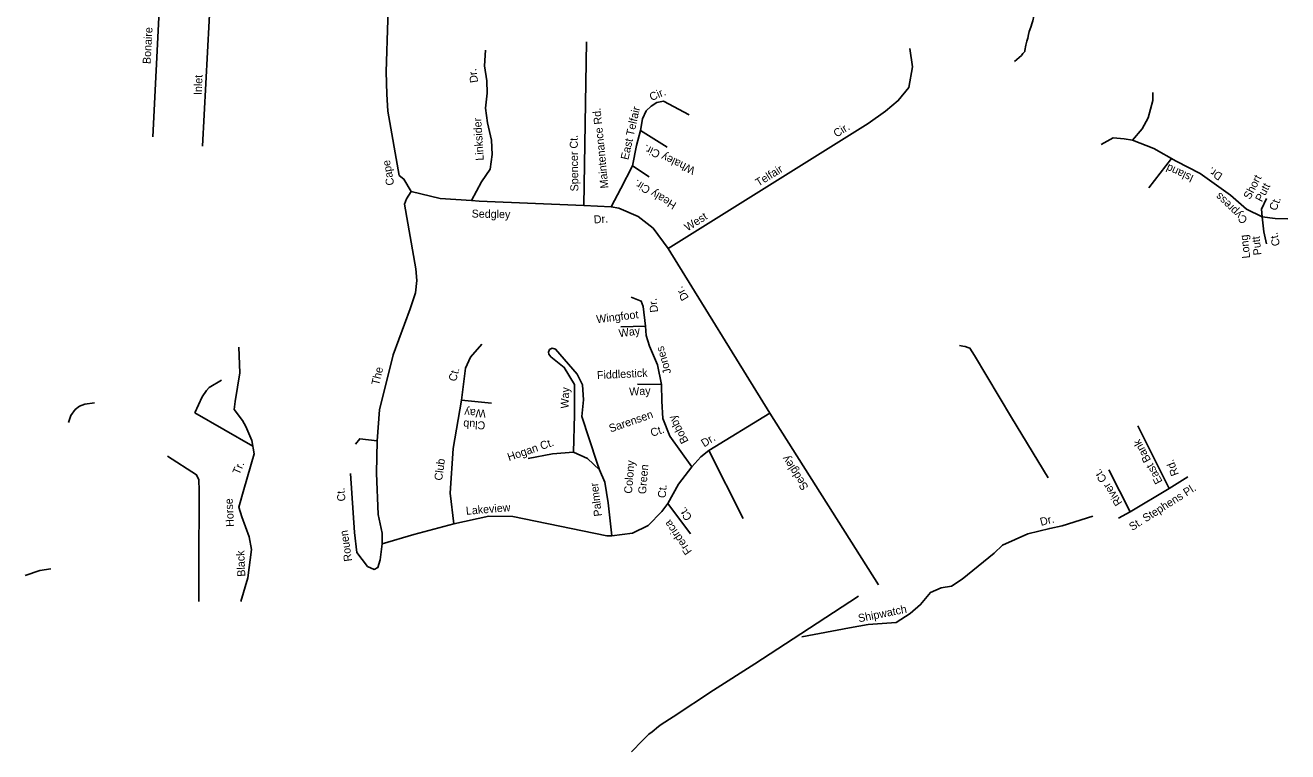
# Model space of a CAD drawing. Extents: x 2308163 to 2335412, y -96774 to 125428.
# Drawn here: x 2324630 to 2334985, y -96774 to -90814 of the extents above; entities that cross this region are included whole.
import ezdxf

# ---------------------------------------------------------------- set-up
doc = ezdxf.new("R2010")
doc.units = 0
doc.layers.add('Old_Level_10', color=7, linetype='Continuous')
doc.layers.add('Old_Level_35', color=7, linetype='Continuous')

msp = doc.modelspace()

# ---------------------------------------------------------------- linework, layer by layer
at = {"layer": 'Old_Level_35'}
for points in [[(2326085, -91806), (2326152, -90518), (2326189, -90072), (2326190, -89610), (2326229, -89135), (2326193, -88679), (2326196, -88378), (2326271, -88124), (2326301, -87898), (2326305, -87568)], [(2325677, -91728), (2325865, -87971), (2325825, -87640)], [(2327796, -92178), (2327736, -92075), (2327696, -92045), (2327605, -91518), (2327597, -91379), (2327591, -91195), (2327605, -90768), (2327601, -90659), (2327585, -90390), (2327568, -90164), (2327576, -90042), (2327622, -89922), (2327719, -89796), (2327790, -89673), (2327855, -89503), (2327932, -89196), (2328010, -88880), (2328116, -88473), (2328205, -88083), (2328236, -87862)], [(2332847, -90937), (2332852, -90920), (2332858, -90890), (2332865, -90865), (2332878, -90829), (2332889, -90795), (2332895, -90777), (2332897, -90763), (2332900, -90752), (2332898, -90734), (2332900, -90714), (2332892, -90635), (2332880, -90503), (2332863, -90354), (2332856, -90304), (2332856, -90238), (2332854, -90160), (2332859, -90030), (2332866, -89826), (2332879, -89537), (2332887, -89332)], [(2329211, -92291), (2329233, -90949)], [(2329903, -92646), (2331544, -91619), (2331686, -91519), (2331790, -91431), (2331877, -91325), (2331908, -91154), (2331884, -91003)], [(2332743, -91110), (2332800, -91061), (2332813, -91046), (2332823, -91034), (2332829, -91028), (2332829, -91020), (2332838, -90976), (2332845, -90944), (2332847, -90937)], [(2328405, -91018), (2328396, -91147), (2328417, -91269), (2328418, -91370), (2328405, -91495), (2328422, -91613), (2328455, -91757), (2328459, -91874), (2328443, -91995), (2328372, -92097), (2328291, -92251)], [(2333711, -91755), (2333790, -91664), (2333840, -91573), (2333879, -91430), (2333877, -91366)], [(2329437, -92303), (2329514, -92152), (2329612, -91967), (2329643, -91801), (2329677, -91676), (2329693, -91581), (2329724, -91515), (2329763, -91478), (2329810, -91446), (2329865, -91436), (2330075, -91548)], [(2329677, -91676), (2329894, -91814)], [(2333455, -91793), (2333554, -91737), (2333643, -91744), (2333711, -91755), (2333887, -91825), (2334070, -91929), (2334266, -92029), (2334515, -92207), (2334647, -92322), (2334776, -92386), (2334770, -92322), (2334811, -92234)], [(2333846, -92146), (2334030, -91906)], [(2329612, -91967), (2329748, -92056)], [(2327796, -92178), (2327756, -92238), (2327742, -92280), (2327833, -92811), (2327842, -92907), (2327830, -93008), (2327788, -93140), (2327649, -93517), (2327537, -93968), (2327516, -94223), (2327511, -94487), (2327524, -94827), (2327557, -94979), (2327558, -95067), (2327541, -95200), (2327522, -95262), (2327492, -95278), (2327438, -95255), (2327350, -95139), (2327330, -94975), (2327297, -94492)], [(2330097, -94435), (2330171, -94353), (2330236, -94301), (2330737, -93996), (2329903, -92646), (2329779, -92478), (2329657, -92382), (2329500, -92314), (2329437, -92303), (2329211, -92291), (2328354, -92257), (2328291, -92251), (2328032, -92234), (2327796, -92178)], [(2334776, -92386), (2334789, -92509), (2334811, -92608)], [(2334776, -92386), (2334882, -92398), (2334985, -92402)], [(2327558, -95067), (2327816, -94992), (2328146, -94903), (2328433, -94841), (2328630, -94844), (2329201, -94961), (2329400, -95001), (2329442, -95003), (2329611, -94979), (2329739, -94917), (2329851, -94803), (2329900, -94738), (2329988, -94577), (2330097, -94435), (2329917, -94185), (2329859, -94041), (2329852, -93898), (2329848, -93760), (2329816, -93600), (2329750, -93447), (2329724, -93358), (2329718, -93282), (2329698, -93122), (2329683, -93076), (2329600, -93044)], [(2329718, -93282), (2329516, -93288)], [(2326398, -95542), (2326457, -95348), (2326487, -95114), (2326468, -95011), (2326408, -94847), (2326381, -94766), (2326423, -94621), (2326507, -94330), (2326488, -94220), (2326439, -94104), (2326413, -94056), (2326343, -93965), (2326353, -93900), (2326390, -93666), (2326383, -93454)], [(2328146, -94903), (2328114, -94653), (2328139, -94285), (2328207, -93889), (2328241, -93627), (2328282, -93536), (2328374, -93430)], [(2329127, -94315), (2329134, -94009), (2329134, -93762), (2329051, -93621), (2328940, -93533), (2328924, -93512), (2328921, -93495), (2328930, -93474), (2328951, -93463), (2328980, -93472), (2329158, -93675), (2329201, -93764), (2329209, -93886), (2329196, -94024), (2329317, -94397), (2329340, -94460)], [(2333019, -94526), (2332720, -94031), (2332415, -93523), (2332378, -93464), (2332362, -93456), (2332340, -93448), (2332320, -93445), (2332294, -93440)], [(2326021, -93992), (2326082, -93863), (2326117, -93811), (2326138, -93785), (2326239, -93725)], [(2329848, -93760), (2329651, -93757)], [(2324986, -94073), (2325005, -94016), (2325040, -93966), (2325076, -93939), (2325120, -93921), (2325198, -93911)], [(2328207, -93889), (2328454, -93915)], [(2326021, -93992), (2326496, -94266)], [(2330737, -93996), (2331627, -95404)], [(2333755, -94100), (2334013, -94614), (2334165, -94517)], [(2327516, -94223), (2327374, -94206), (2327339, -94251)], [(2329442, -95003), (2329410, -94731), (2329383, -94562), (2329340, -94460), (2329243, -94369), (2329127, -94315), (2328955, -94330), (2328756, -94369)], [(2330236, -94301), (2330519, -94860)], [(2325796, -94348), (2326035, -94501), (2326054, -94542), (2326057, -94631), (2326055, -95271), (2326055, -95541)], [(2333692, -94806), (2333517, -94461)], [(2334013, -94614), (2333692, -94806), (2333597, -94858)], [(2329900, -94738), (2330087, -94987)], [(2331000, -95830), (2331390, -95758), (2331544, -95729), (2331774, -95712), (2331887, -95639), (2331974, -95566), (2332054, -95467), (2332142, -95428), (2332227, -95414), (2332314, -95357), (2332576, -95145), (2332646, -95080), (2332854, -94985), (2333033, -94941), (2333136, -94919), (2333385, -94842)], [(2324630, -95327), (2324749, -95286), (2324840, -95274)], [(2331465, -95497), (2330992, -95807), (2330614, -96052), (2330276, -96269), (2329945, -96487), (2329847, -96551), (2329825, -96565), (2329772, -96609), (2329745, -96629), (2329692, -96680), (2329603, -96774)]]:
    msp.add_lwpolyline(points, dxfattribs=at)

# ---------------------------------------------------------------- texts
at = {"layer": 'Old_Level_10'}
for s, height, rotation, p in [('Bonaire', 65.6, 86.8529, (2325658, -91133)), ('Inlet', 65.6, 87.8162, (2326078, -91387)), ('Dr.', 65.6, 98.3115, (2328345, -91281)), ('Cir.', 65.6, 22.8854, (2329766, -91436)), ('Maintenance Rd.', 65.62, 95.7048, (2329414, -92149)), ('East Telfair ', 65.62, 77.2768, (2329576, -91922)), ('Linksider', 65.6, 93.4684, (2328391, -91922)), ('Cir.', 65.6, 31.7692, (2331284, -91736)), ('Spencer Ct.', 65.62, 90.7324, (2329167, -92176)), ('Whaley Cir.', 65.62, 154.835, (2330131, -91983)), ('Cape', 65.6, 99.9628, (2327657, -92122)), ('Telfair', 65.6, 31.8069, (2330644, -92139)), (' Island ', 65.6, 155.2034, (2334241, -92058)), ('Dr.', 65.6, 146.8638, (2334456, -92037)), ('Short', 65.6, 62.5056, (2334675, -92248)), ('Healy Cir.', 65.6, 149.1209, (2329977, -92273)), ('Putt', 65.6, 62.5056, (2334772, -92268)), ('Cypress', 65.6, 136.1992, (2334661, -92404)), ('Ct.', 65.6, 68.6681, (2334890, -92340)), ('Sedgley', 65.6, 358.9794, (2328291, -92391)), ('West', 65.6, 32.3643, (2330062, -92506)), ('Dr.', 65.6, 3.7721, (2329295, -92440)), ('Long', 65.6, 95.9768, (2334677, -92723)), ('Putt', 65.6, 95.9768, (2334770, -92697)), ('Ct.', 65.6, 101.7692, (2334922, -92618)), ('Dr.', 65.6, 121.0201, (2330075, -93049)), ('Dr.', 65.6, 96.5311, (2329821, -93166)), ('Wingfoot ', 65.6, 6.8876, (2329318, -93258)), ('Way', 65.6, 8.3091, (2329503, -93374)), ('Jones', 65.6, 106.3222, (2329929, -93665)), ('The ', 65.6, 76.327, (2327531, -93772)), ('Ct.', 65.6, 75.0685, (2328163, -93740)), ('Fiddlestick', 65.62, 2.8383, (2329321, -93717)), ('Way', 65.6, 87.7119, (2329086, -93959)), ('Way', 65.6, 2.8383, (2329585, -93852)), ('Way', 65.6, 176.6967, (2328409, -93968)), ('Sarensen', 65.6, 19.2289, (2329431, -94155)), ('Club', 65.6, 176.6967, (2328405, -94065)), ('Ct.', 65.6, 19.2289, (2329771, -94191)), ('Bobby', 65.6, 117.1145, (2330072, -94226)), ('Hogan Ct.', 65.6, 19.0033, (2328598, -94390)), ('Dr.', 65.6, 32.3018, (2330199, -94277)), ('East Bank', 65.6, 118.3259, (2333960, -94556)), ('Tr.', 65.6, 66.8835, (2326387, -94506)), ('Club ', 65.6, 82.3139, (2328049, -94552)), ('Colony', 65.6, 85.3278, (2329606, -94658)), ('Green ', 65.6, 85.3278, (2329721, -94662)), ('Sedgley', 65.6, 122.9112, (2331057, -94602)), ('Rd.', 65.6, 110.7645, (2334093, -94497)), ('River Ct.', 65.6, 123.4059, (2333631, -94730)), ('Ct.', 65.6, 94.6733, (2327257, -94717)), ('Palmer', 65.6, 97.0173, (2329361, -94839)), ('Ct.', 65.6, 85.3278, (2329883, -94694)), ('St. Stephens Pl.', 65.62, 32.4762, (2333709, -94963)), ('Horse', 65.6, 92.966, (2326343, -94927)), ('Lakeview', 65.6, 4.7502, (2328247, -94830)), ('Ct.', 65.6, 124.4823, (2330103, -94850)), ('Fredrica', 65.6, 124.4823, (2330101, -95130)), ('Dr.', 65.6, 14.4843, (2332962, -94921)), ('Rouen', 65.6, 98.3217, (2327311, -95208)), ('Black', 65.6, 92.67, (2326436, -95336)), ('Shipwatch', 65.6, 11.3903, (2331468, -95712))]:
    msp.add_text(s, height=height, rotation=rotation, dxfattribs=at).set_placement(p)

doc.saveas('drawing.dxf')
